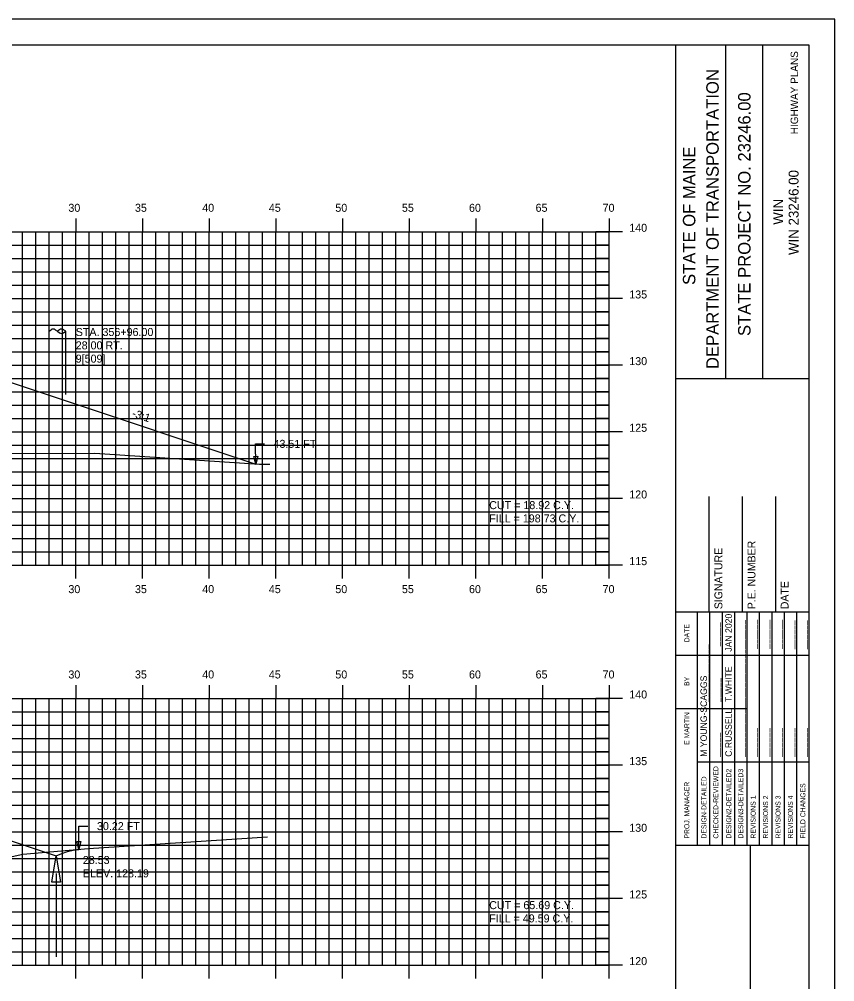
# Model space of a CAD drawing. Extents: x 1145638 to 1145808, y 608981 to 609091.
# Drawn here: x 1145746.4 to 1145807.6, y 609019.1 to 609091.3 of the extents above; entities that cross this region are included whole.
import ezdxf

# ---------------------------------------------------------------- set-up
doc = ezdxf.new("R2010")
doc.units = 0
for name, color, linetype in [('ANNOTATION', 7, 'Continuous'), ('BORDER', 7, 'Continuous'), ('D_Drainage_Ditch_Line', 7, 'Continuous'), ('D_Roadway_SlopeLines', 7, 'Continuous'), ('D_Text_Standard', 7, 'Continuous'), ('D_Utilities_Pole_Joint_Rt', 7, 'Continuous'), ('H_V ANNOTATION', 7, 'Continuous'), ('HIGHWAY_TITLE', 7, 'Continuous'), ('MAJOR', 7, 'Continuous'), ('MINOR', 7, 'Continuous'), ('PLOT BOUNDARY', 7, 'Continuous'), ('S_Roadway_Centerline', 7, 'Continuous')]:
    doc.layers.add(name, color=color, linetype=linetype)

msp = doc.modelspace()

# ---------------------------------------------------------------- linework, layer by layer
for points in [[(1145681.816, 609061.135), (1145686.815, 609062.801), (1145689.815, 609063.801), (1145696.986, 609066.192), (1145696.987, 609066.192), (1145709.645, 609066.698), (1145720.645, 609066.918), (1145731.645, 609066.698), (1145738.645, 609066.418), (1145746.177, 609063.907), (1145749.177, 609062.907), (1145764.157, 609057.914)], [(1145681.258, 609032.341), (1145682.508, 609032.231), (1145683.758, 609031.973), (1145685.008, 609031.568), (1145686.258, 609031.017), (1145691.284, 609028.504), (1145694.284, 609029.504), (1145701.76, 609031.996), (1145701.761, 609031.996), (1145709.645, 609032.311), (1145720.645, 609032.531), (1145731.645, 609032.311), (1145738.645, 609032.031), (1145746.177, 609029.52), (1145749.177, 609028.52), (1145749.6, 609028.71), (1145750.023, 609028.855), (1145750.446, 609028.957), (1145750.869, 609029.014)]]:
    msp.add_lwpolyline(points)
at = {"layer": 'BORDER'}
for p, q in [((1145795.645, 608984.335), (1145795.645, 609089.335)), ((1145799.374, 609064.332), (1145799.374, 609089.332)), ((1145802.169, 609064.332), (1145802.169, 609089.332)), ((1145795.646, 609064.329), (1145805.645, 609064.329)), ((1145798.145, 609046.838), (1145798.145, 609055.485)), ((1145800.645, 609046.838), (1145800.645, 609055.485)), ((1145803.145, 609046.838), (1145803.145, 609055.485)), ((1145795.645, 609046.838), (1145805.645, 609046.838)), ((1145795.645, 609029.338), (1145805.645, 609029.338)), ((1145801.236, 608994.338), (1145801.236, 609029.338))]:
    msp.add_line(p, q, dxfattribs=at)
msp.add_lwpolyline([(1145645.645, 608984.335), (1145805.645, 608984.335), (1145805.645, 609089.335), (1145645.645, 609089.335)], close=True, dxfattribs=at)
for points in [[(1145797.26, 609043.588), (1145797.26, 609046.838)], [(1145798.193, 609029.341), (1145798.193, 609046.838)], [(1145799.124, 609046.838), (1145799.124, 609029.341)], [(1145800.056, 609029.341), (1145800.056, 609046.838)], [(1145800.988, 609029.341), (1145800.988, 609046.838)], [(1145801.919, 609029.341), (1145801.919, 609046.838)], [(1145802.851, 609029.341), (1145802.851, 609046.838)], [(1145803.783, 609029.341), (1145803.783, 609046.838)], [(1145804.715, 609029.341), (1145804.715, 609046.838)], [(1145797.261, 609029.341), (1145797.261, 609046.132)], [(1145795.645, 609043.588), (1145805.645, 609043.588)], [(1145795.645, 609039.588), (1145797.261, 609039.588)], [(1145797.26, 609039.588), (1145800.987, 609039.588)], [(1145797.26, 609035.588), (1145805.645, 609035.588)]]:
    msp.add_lwpolyline(points, dxfattribs=at)
at = {"layer": 'D_Drainage_Ditch_Line'}
msp.add_line((1145749.177, 609027.208), (1145749.177, 609020.964), dxfattribs=at)
msp.add_lwpolyline([(1145749.505, 609026.552), (1145748.849, 609026.552), (1145749.177, 609028.52)], close=True, dxfattribs=at)
at = {"layer": 'D_Roadway_SlopeLines'}
for points in [[(1145746.177, 609063.907), (1145749.177, 609062.907)], [(1145749.177, 609062.907), (1145764.157, 609057.914)], [(1145746.177, 609029.52), (1145749.177, 609028.52)], [(1145749.177, 609028.52), (1145749.6, 609028.71), (1145750.023, 609028.855), (1145750.446, 609028.957), (1145750.869, 609029.014)]]:
    msp.add_lwpolyline(points, dxfattribs=at)
at = {"layer": 'D_Text_Standard'}
for points in [[(1145764.157, 609057.914), (1145764.115, 609059.431), (1145764.795, 609059.431)], [(1145750.869, 609029.014), (1145750.877, 609030.761), (1145751.557, 609030.761)]]:
    msp.add_lwpolyline(points, dxfattribs=at)
for points in [[(1145764.157, 609057.914), (1145763.995, 609058.492), (1145764.286, 609058.5)], [(1145750.869, 609029.014), (1145750.726, 609029.596), (1145751.017, 609029.595)]]:
    msp.add_lwpolyline(points, close=True, dxfattribs=at)
at = {"layer": 'D_Utilities_Pole_Joint_Rt'}
for p, q in [((1145748.645, 609067.88), (1145748.801, 609067.99)), ((1145748.645, 609063.122), (1145748.645, 609067.88)), ((1145749.114, 609067.99), (1145749.27, 609067.88)), ((1145749.426, 609067.99), (1145749.27, 609067.88)), ((1145749.27, 609067.88), (1145749.426, 609067.769)), ((1145749.895, 609067.88), (1145749.739, 609067.99)), ((1145749.739, 609067.769), (1145749.895, 609067.88)), ((1145749.895, 609063.122), (1145749.895, 609067.88))]:
    msp.add_line(p, q, dxfattribs=at)
for centre, start, end in [((1145748.957, 609067.769), 90, 125.26439), ((1145748.957, 609067.769), 54.73561, 90), ((1145749.582, 609067.769), 90, 125.26439), ((1145749.582, 609067.99), 234.73561, 270), ((1145749.582, 609067.769), 54.73561, 90), ((1145749.582, 609067.99), 270, 305.26439)]:
    msp.add_arc(centre, 0.271, start, end, dxfattribs=at)
at = {"layer": 'MAJOR'}
for p, q in [((1145750.645, 609076.337), (1145750.645, 609075.335)), ((1145755.645, 609076.337), (1145755.645, 609075.335)), ((1145760.645, 609076.337), (1145760.645, 609075.335)), ((1145765.645, 609076.337), (1145765.645, 609075.335)), ((1145770.645, 609076.337), (1145770.645, 609075.335)), ((1145775.645, 609076.337), (1145775.645, 609075.335)), ((1145780.645, 609076.337), (1145780.645, 609075.335)), ((1145785.645, 609076.337), (1145785.645, 609075.335)), ((1145790.645, 609076.337), (1145790.645, 609075.335)), ((1145650.645, 609075.335), (1145790.645, 609075.335)), ((1145650.645, 609075.335), (1145790.645, 609075.335)), ((1145750.645, 609050.335), (1145750.645, 609075.335)), ((1145755.645, 609050.335), (1145755.645, 609075.335)), ((1145760.645, 609050.335), (1145760.645, 609075.335)), ((1145765.645, 609050.335), (1145765.645, 609075.335)), ((1145770.645, 609050.335), (1145770.645, 609075.335)), ((1145775.645, 609050.335), (1145775.645, 609075.335)), ((1145780.645, 609050.335), (1145780.645, 609075.335)), ((1145785.645, 609050.335), (1145785.645, 609075.335)), ((1145791.647, 609075.335), (1145789.643, 609075.335)), ((1145790.645, 609050.335), (1145790.645, 609075.335)), ((1145790.645, 609050.335), (1145790.645, 609075.335)), ((1145650.645, 609070.335), (1145790.645, 609070.335)), ((1145791.647, 609070.335), (1145789.643, 609070.335)), ((1145650.645, 609065.335), (1145790.645, 609065.335)), ((1145791.647, 609065.335), (1145789.643, 609065.335)), ((1145650.645, 609060.335), (1145790.645, 609060.335)), ((1145791.647, 609060.335), (1145789.643, 609060.335)), ((1145650.645, 609055.335), (1145790.645, 609055.335)), ((1145791.647, 609055.335), (1145789.643, 609055.335)), ((1145650.645, 609050.335), (1145790.645, 609050.335)), ((1145650.645, 609050.335), (1145790.645, 609050.335)), ((1145750.645, 609049.333), (1145750.645, 609050.335)), ((1145755.645, 609049.333), (1145755.645, 609050.335)), ((1145760.645, 609049.333), (1145760.645, 609050.335)), ((1145765.645, 609049.333), (1145765.645, 609050.335)), ((1145770.645, 609049.333), (1145770.645, 609050.335)), ((1145775.645, 609049.333), (1145775.645, 609050.335)), ((1145780.645, 609049.333), (1145780.645, 609050.335)), ((1145785.645, 609049.333), (1145785.645, 609050.335)), ((1145791.647, 609050.335), (1145789.643, 609050.335)), ((1145790.645, 609049.333), (1145790.645, 609050.335)), ((1145750.645, 609041.337), (1145750.645, 609040.335)), ((1145755.645, 609041.337), (1145755.645, 609040.335)), ((1145760.645, 609041.337), (1145760.645, 609040.335)), ((1145765.645, 609041.337), (1145765.645, 609040.335)), ((1145770.645, 609041.337), (1145770.645, 609040.335)), ((1145775.645, 609041.337), (1145775.645, 609040.335)), ((1145780.645, 609041.337), (1145780.645, 609040.335)), ((1145785.645, 609041.337), (1145785.645, 609040.335)), ((1145790.645, 609041.337), (1145790.645, 609040.335)), ((1145650.645, 609040.335), (1145790.645, 609040.335)), ((1145650.645, 609040.335), (1145790.645, 609040.335)), ((1145750.645, 609020.335), (1145750.645, 609040.335)), ((1145755.645, 609020.335), (1145755.645, 609040.335)), ((1145760.645, 609020.335), (1145760.645, 609040.335)), ((1145765.645, 609020.335), (1145765.645, 609040.335)), ((1145770.645, 609020.335), (1145770.645, 609040.335)), ((1145775.645, 609020.335), (1145775.645, 609040.335)), ((1145780.645, 609020.335), (1145780.645, 609040.335)), ((1145785.645, 609020.335), (1145785.645, 609040.335)), ((1145791.647, 609040.335), (1145789.643, 609040.335)), ((1145790.645, 609020.335), (1145790.645, 609040.335)), ((1145790.645, 609020.335), (1145790.645, 609040.335)), ((1145650.645, 609035.335), (1145790.645, 609035.335)), ((1145791.647, 609035.335), (1145789.643, 609035.335)), ((1145650.645, 609030.335), (1145790.645, 609030.335)), ((1145791.647, 609030.335), (1145789.643, 609030.335)), ((1145650.645, 609025.335), (1145790.645, 609025.335)), ((1145791.647, 609025.335), (1145789.643, 609025.335)), ((1145650.645, 609020.335), (1145790.645, 609020.335)), ((1145650.645, 609020.335), (1145790.645, 609020.335)), ((1145750.645, 609019.333), (1145750.645, 609020.335)), ((1145755.645, 609019.333), (1145755.645, 609020.335)), ((1145760.645, 609019.333), (1145760.645, 609020.335)), ((1145765.645, 609019.333), (1145765.645, 609020.335)), ((1145770.645, 609019.333), (1145770.645, 609020.335)), ((1145775.645, 609019.333), (1145775.645, 609020.335)), ((1145780.645, 609019.333), (1145780.645, 609020.335)), ((1145785.645, 609019.333), (1145785.645, 609020.335)), ((1145791.647, 609020.335), (1145789.643, 609020.335)), ((1145790.645, 609019.333), (1145790.645, 609020.335))]:
    msp.add_line(p, q, dxfattribs=at)
at = {"layer": 'MINOR'}
for p, q in [((1145746.645, 609050.335), (1145746.645, 609075.335)), ((1145747.645, 609050.335), (1145747.645, 609075.335)), ((1145748.645, 609050.335), (1145748.645, 609075.335)), ((1145749.645, 609050.335), (1145749.645, 609075.335)), ((1145751.645, 609050.335), (1145751.645, 609075.335)), ((1145752.645, 609050.335), (1145752.645, 609075.335)), ((1145753.645, 609050.335), (1145753.645, 609075.335)), ((1145754.645, 609050.335), (1145754.645, 609075.335)), ((1145756.645, 609050.335), (1145756.645, 609075.335)), ((1145757.645, 609050.335), (1145757.645, 609075.335)), ((1145758.645, 609050.335), (1145758.645, 609075.335)), ((1145759.645, 609050.335), (1145759.645, 609075.335)), ((1145761.645, 609050.335), (1145761.645, 609075.335)), ((1145762.645, 609050.335), (1145762.645, 609075.335)), ((1145763.645, 609050.335), (1145763.645, 609075.335)), ((1145764.645, 609050.335), (1145764.645, 609075.335)), ((1145766.645, 609050.335), (1145766.645, 609075.335)), ((1145767.645, 609050.335), (1145767.645, 609075.335)), ((1145768.645, 609050.335), (1145768.645, 609075.335)), ((1145769.645, 609050.335), (1145769.645, 609075.335)), ((1145771.645, 609050.335), (1145771.645, 609075.335)), ((1145772.645, 609050.335), (1145772.645, 609075.335)), ((1145773.645, 609050.335), (1145773.645, 609075.335)), ((1145774.645, 609050.335), (1145774.645, 609075.335)), ((1145776.645, 609050.335), (1145776.645, 609075.335)), ((1145777.645, 609050.335), (1145777.645, 609075.335)), ((1145778.645, 609050.335), (1145778.645, 609075.335)), ((1145779.645, 609050.335), (1145779.645, 609075.335)), ((1145781.645, 609050.335), (1145781.645, 609075.335)), ((1145782.645, 609050.335), (1145782.645, 609075.335)), ((1145783.645, 609050.335), (1145783.645, 609075.335)), ((1145784.645, 609050.335), (1145784.645, 609075.335)), ((1145786.645, 609050.335), (1145786.645, 609075.335)), ((1145787.645, 609050.335), (1145787.645, 609075.335)), ((1145788.645, 609050.335), (1145788.645, 609075.335)), ((1145789.645, 609050.335), (1145789.645, 609075.335)), ((1145650.645, 609074.335), (1145790.645, 609074.335)), ((1145790.645, 609074.335), (1145789.643, 609074.335)), ((1145650.645, 609073.335), (1145790.645, 609073.335)), ((1145790.645, 609073.335), (1145789.643, 609073.335)), ((1145650.645, 609072.335), (1145790.645, 609072.335)), ((1145790.645, 609072.335), (1145789.643, 609072.335)), ((1145650.645, 609071.335), (1145790.645, 609071.335)), ((1145790.645, 609071.335), (1145789.643, 609071.335)), ((1145650.645, 609069.335), (1145790.645, 609069.335)), ((1145790.645, 609069.335), (1145789.643, 609069.335)), ((1145650.645, 609068.335), (1145790.645, 609068.335)), ((1145790.645, 609068.335), (1145789.643, 609068.335)), ((1145650.645, 609067.335), (1145790.645, 609067.335)), ((1145790.645, 609067.335), (1145789.643, 609067.335)), ((1145650.645, 609066.335), (1145790.645, 609066.335)), ((1145790.645, 609066.335), (1145789.643, 609066.335)), ((1145650.645, 609064.335), (1145790.645, 609064.335)), ((1145790.645, 609064.335), (1145789.643, 609064.335)), ((1145650.645, 609063.335), (1145790.645, 609063.335)), ((1145790.645, 609063.335), (1145789.643, 609063.335)), ((1145650.645, 609062.335), (1145790.645, 609062.335)), ((1145790.645, 609062.335), (1145789.643, 609062.335)), ((1145650.645, 609061.335), (1145790.645, 609061.335)), ((1145790.645, 609061.335), (1145789.643, 609061.335)), ((1145650.645, 609059.335), (1145790.645, 609059.335)), ((1145790.645, 609059.335), (1145789.643, 609059.335)), ((1145650.645, 609058.335), (1145790.645, 609058.335)), ((1145790.645, 609058.335), (1145789.643, 609058.335)), ((1145650.645, 609057.335), (1145790.645, 609057.335)), ((1145790.645, 609057.335), (1145789.643, 609057.335)), ((1145650.645, 609056.335), (1145790.645, 609056.335)), ((1145790.645, 609056.335), (1145789.643, 609056.335)), ((1145650.645, 609054.335), (1145790.645, 609054.335)), ((1145790.645, 609054.335), (1145789.643, 609054.335)), ((1145650.645, 609053.335), (1145790.645, 609053.335)), ((1145790.645, 609053.335), (1145789.643, 609053.335)), ((1145650.645, 609052.335), (1145790.645, 609052.335)), ((1145790.645, 609052.335), (1145789.643, 609052.335)), ((1145650.645, 609051.335), (1145790.645, 609051.335)), ((1145790.645, 609051.335), (1145789.643, 609051.335)), ((1145746.645, 609020.335), (1145746.645, 609040.335)), ((1145747.645, 609020.335), (1145747.645, 609040.335)), ((1145748.645, 609020.335), (1145748.645, 609040.335)), ((1145749.645, 609020.335), (1145749.645, 609040.335)), ((1145751.645, 609020.335), (1145751.645, 609040.335)), ((1145752.645, 609020.335), (1145752.645, 609040.335)), ((1145753.645, 609020.335), (1145753.645, 609040.335)), ((1145754.645, 609020.335), (1145754.645, 609040.335)), ((1145756.645, 609020.335), (1145756.645, 609040.335)), ((1145757.645, 609020.335), (1145757.645, 609040.335)), ((1145758.645, 609020.335), (1145758.645, 609040.335)), ((1145759.645, 609020.335), (1145759.645, 609040.335)), ((1145761.645, 609020.335), (1145761.645, 609040.335)), ((1145762.645, 609020.335), (1145762.645, 609040.335)), ((1145763.645, 609020.335), (1145763.645, 609040.335)), ((1145764.645, 609020.335), (1145764.645, 609040.335)), ((1145766.645, 609020.335), (1145766.645, 609040.335)), ((1145767.645, 609020.335), (1145767.645, 609040.335)), ((1145768.645, 609020.335), (1145768.645, 609040.335)), ((1145769.645, 609020.335), (1145769.645, 609040.335)), ((1145771.645, 609020.335), (1145771.645, 609040.335)), ((1145772.645, 609020.335), (1145772.645, 609040.335)), ((1145773.645, 609020.335), (1145773.645, 609040.335)), ((1145774.645, 609020.335), (1145774.645, 609040.335)), ((1145776.645, 609020.335), (1145776.645, 609040.335)), ((1145777.645, 609020.335), (1145777.645, 609040.335)), ((1145778.645, 609020.335), (1145778.645, 609040.335)), ((1145779.645, 609020.335), (1145779.645, 609040.335)), ((1145781.645, 609020.335), (1145781.645, 609040.335)), ((1145782.645, 609020.335), (1145782.645, 609040.335)), ((1145783.645, 609020.335), (1145783.645, 609040.335)), ((1145784.645, 609020.335), (1145784.645, 609040.335)), ((1145786.645, 609020.335), (1145786.645, 609040.335)), ((1145787.645, 609020.335), (1145787.645, 609040.335)), ((1145788.645, 609020.335), (1145788.645, 609040.335)), ((1145789.645, 609020.335), (1145789.645, 609040.335)), ((1145650.645, 609039.335), (1145790.645, 609039.335)), ((1145790.645, 609039.335), (1145789.643, 609039.335)), ((1145650.645, 609038.335), (1145790.645, 609038.335)), ((1145790.645, 609038.335), (1145789.643, 609038.335)), ((1145650.645, 609037.335), (1145790.645, 609037.335)), ((1145790.645, 609037.335), (1145789.643, 609037.335)), ((1145650.645, 609036.335), (1145790.645, 609036.335)), ((1145790.645, 609036.335), (1145789.643, 609036.335)), ((1145650.645, 609034.335), (1145790.645, 609034.335)), ((1145790.645, 609034.335), (1145789.643, 609034.335)), ((1145650.645, 609033.335), (1145790.645, 609033.335)), ((1145790.645, 609033.335), (1145789.643, 609033.335)), ((1145650.645, 609032.335), (1145790.645, 609032.335)), ((1145790.645, 609032.335), (1145789.643, 609032.335)), ((1145650.645, 609031.335), (1145790.645, 609031.335)), ((1145790.645, 609031.335), (1145789.643, 609031.335)), ((1145650.645, 609029.335), (1145790.645, 609029.335)), ((1145790.645, 609029.335), (1145789.643, 609029.335)), ((1145650.645, 609028.335), (1145790.645, 609028.335)), ((1145790.645, 609028.335), (1145789.643, 609028.335)), ((1145650.645, 609027.335), (1145790.645, 609027.335)), ((1145790.645, 609027.335), (1145789.643, 609027.335)), ((1145650.645, 609026.335), (1145790.645, 609026.335)), ((1145790.645, 609026.335), (1145789.643, 609026.335)), ((1145650.645, 609024.335), (1145790.645, 609024.335)), ((1145790.645, 609024.335), (1145789.643, 609024.335)), ((1145650.645, 609023.335), (1145790.645, 609023.335)), ((1145790.645, 609023.335), (1145789.643, 609023.335)), ((1145650.645, 609022.335), (1145790.645, 609022.335)), ((1145790.645, 609022.335), (1145789.643, 609022.335)), ((1145650.645, 609021.335), (1145790.645, 609021.335)), ((1145790.645, 609021.335), (1145789.643, 609021.335))]:
    msp.add_line(p, q, dxfattribs=at)
at = {"layer": 'PLOT BOUNDARY'}
msp.add_lwpolyline([(1145637.552, 608981.276), (1145807.552, 608981.276), (1145807.552, 609091.276), (1145637.552, 609091.276)], close=True, dxfattribs=at)
at = {"layer": 'S_Roadway_Centerline'}
for points in [[(1145670.563, 609061.952), (1145685.175, 609060.891), (1145685.737, 609060.851), (1145688.296, 609060.867), (1145697.073, 609061.142), (1145704.489, 609062.703), (1145705.144, 609062.915), (1145707.28, 609063.094), (1145707.355, 609063.105), (1145707.651, 609063.114), (1145718.66, 609063.546), (1145728.46, 609063.36), (1145729.217, 609063.34), (1145732.934, 609062.767), (1145733.208, 609062.71), (1145735.659, 609061.739), (1145744.076, 609058.7), (1145752.065, 609058.73), (1145764.42, 609057.896), (1145765.193, 609057.913)], [(1145669.136, 609032.753), (1145680.62, 609032.361), (1145689.164, 609032.105), (1145700.503, 609028.355), (1145700.592, 609028.328), (1145700.97, 609028.382), (1145704.281, 609028.863), (1145704.322, 609028.867), (1145707.646, 609029.095), (1145707.961, 609029.103), (1145718.638, 609029.518), (1145719.177, 609029.498), (1145729.939, 609029.23), (1145730.211, 609029.201), (1145733.672, 609028.828), (1145734.305, 609028.732), (1145741.113, 609027.276), (1145743.374, 609027.926), (1145746.672, 609028.664), (1145751.599, 609029.075), (1145765.021, 609029.966)]]:
    msp.add_lwpolyline(points, dxfattribs=at)

# ---------------------------------------------------------------- texts
at = {"layer": 'ANNOTATION'}
msp.add_text('-3:1', height=0.6, rotation=341.56505, dxfattribs=at).set_placement((1145754.816, 609061.482))
at = {"layer": 'BORDER'}
for s, height, p in [('DEPARTMENT OF TRANSPORTATION', 0.93176, (1145798.852, 609065.041)), ('STATE PROJECT NO. 23246.00', 0.93176, (1145801.237, 609067.517)), ('STATE OF MAINE', 0.93176, (1145797.101, 609071.347)), ('WIN 23246.00', 0.74527, (1145804.841, 609073.596)), ('WIN', 0.7453, (1145803.682, 609075.865)), ('SIGNATURE', 0.5906, (1145799.126, 609047.03)), ('P.E. NUMBER', 0.59055, (1145801.606, 609047.03)), ('DATE', 0.5906, (1145804.086, 609047.03)), ('JAN 2020', 0.4845, (1145799.832, 609043.843)), ('DATE', 0.3714, (1145796.65, 609044.544)), ('_____', 0.4845, (1145798.863, 609044.243)), ('______', 0.4845, (1145800.726, 609044.063)), ('______', 0.4845, (1145801.658, 609044.065)), ('______', 0.4845, (1145802.589, 609044.067)), ('______', 0.4845, (1145803.521, 609044.067)), ('______', 0.4845, (1145804.453, 609044.036)), ('______', 0.4845, (1145805.384, 609044.036)), ('____________', 0.48455, (1145797.968, 609040.073)), ('____________', 0.48455, (1145800.726, 609040.073)), ('T.WHITE', 0.4845, (1145799.832, 609040.073)), ('BY', 0.3714, (1145796.65, 609041.273)), ('M YOUNG-SCAGGS', 0.48455, (1145797.968, 609035.961)), ('_____', 0.4845, (1145798.9, 609040.073)), ('____________', 0.48455, (1145800.726, 609035.961)), ('C.RUSSELL', 0.4845, (1145799.832, 609035.961)), ('E MARTIN', 0.3727, (1145796.65, 609036.855)), ('_____', 0.4845, (1145798.863, 609035.961)), ('______', 0.4845, (1145801.658, 609035.961)), ('______', 0.4845, (1145802.589, 609035.961)), ('______', 0.4845, (1145803.521, 609035.961)), ('______', 0.4845, (1145804.453, 609035.961)), ('______', 0.4845, (1145805.384, 609035.961)), ('CHECKED-REVIEWED', 0.37275, (1145798.826, 609029.826)), ('DESIGN2-DETAILED2', 0.37275, (1145799.795, 609029.826)), ('DESIGN3-DETAILED3', 0.37275, (1145800.69, 609029.826)), ('DESIGN-DETAILED', 0.37275, (1145797.932, 609029.826)), ('PROJ. MANAGER', 0.37275, (1145796.65, 609029.826)), ('FIELD CHANGES', 0.37275, (1145805.348, 609029.826)), ('REVISIONS 1', 0.37275, (1145801.621, 609029.826)), ('REVISIONS 2', 0.37275, (1145802.553, 609029.826)), ('REVISIONS 3', 0.37275, (1145803.485, 609029.826)), ('REVISIONS 4', 0.37275, (1145804.416, 609029.826))]:
    msp.add_text(s, height=height, rotation=90, dxfattribs=at).set_placement(p)
at = {"layer": 'D_Text_Standard'}
for s, p in [('STA. 356+96.00', (1145750.645, 609067.52)), ('28.00 RT.', (1145750.645, 609066.518)), ('9[509] ', (1145750.645, 609065.522)), ('43.51 FT', (1145765.475, 609059.131)), ('CUT = 18.92 C.Y.', (1145781.645, 609054.535)), ('FILL = 198.73 C.Y.', (1145781.645, 609053.539)), ('30.22 FT', (1145752.237, 609030.461)), ('28.53', (1145751.177, 609027.92)), ('ELEV. 128.19', (1145751.177, 609026.918)), ('CUT = 65.69 C.Y.', (1145781.645, 609024.535)), ('FILL = 49.59 C.Y.', (1145781.645, 609023.539))]:
    msp.add_text(s, height=0.6, dxfattribs=at).set_placement(p)
at = {"layer": 'H_V ANNOTATION'}
for s, p in [('30', (1145750.094, 609076.835)), ('35', (1145755.086, 609076.835)), ('40', (1145760.131, 609076.835)), ('45', (1145765.123, 609076.835)), ('50', (1145770.11, 609076.835)), ('55', (1145775.102, 609076.835)), ('60', (1145780.131, 609076.835)), ('65', (1145785.123, 609076.835)), ('70', (1145790.147, 609076.835)), ('140', (1145792.145, 609075.335)), ('135', (1145792.145, 609070.335)), ('130', (1145792.145, 609065.335)), ('125', (1145792.145, 609060.335)), ('120', (1145792.145, 609055.335)), ('115', (1145792.145, 609050.335)), ('30', (1145750.094, 609048.235)), ('35', (1145755.086, 609048.235)), ('40', (1145760.131, 609048.235)), ('45', (1145765.123, 609048.235)), ('50', (1145770.11, 609048.235)), ('55', (1145775.102, 609048.235)), ('60', (1145780.131, 609048.235)), ('65', (1145785.123, 609048.235)), ('70', (1145790.147, 609048.235)), ('30', (1145750.094, 609041.835)), ('35', (1145755.086, 609041.835)), ('40', (1145760.131, 609041.835)), ('45', (1145765.123, 609041.835)), ('50', (1145770.11, 609041.835)), ('55', (1145775.102, 609041.835)), ('60', (1145780.131, 609041.835)), ('65', (1145785.123, 609041.835)), ('70', (1145790.147, 609041.835)), ('140', (1145792.145, 609040.335)), ('135', (1145792.145, 609035.335)), ('130', (1145792.145, 609030.335)), ('125', (1145792.145, 609025.335)), ('120', (1145792.145, 609020.335))]:
    msp.add_text(s, height=0.6, dxfattribs=at).set_placement(p)
at = {"layer": 'HIGHWAY_TITLE'}
msp.add_text('HIGHWAY PLANS', height=0.55901, rotation=90, dxfattribs=at).set_placement((1145804.804, 609082.65))

doc.saveas('drawing.dxf')
